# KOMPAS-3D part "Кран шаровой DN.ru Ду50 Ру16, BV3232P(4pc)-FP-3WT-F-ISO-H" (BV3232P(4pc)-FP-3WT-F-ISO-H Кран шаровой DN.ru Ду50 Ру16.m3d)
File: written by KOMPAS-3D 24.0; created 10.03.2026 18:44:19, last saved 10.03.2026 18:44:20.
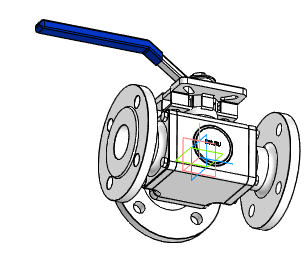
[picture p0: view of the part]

Document properties: Автор: R2D2; Полное имя файла: E:\Работа\Зайцев\BV3232P(4pc)-FP-3WT-F-ISO-H Кран шаровой DN.ru Ду15-100 Ру16\DN50\BV3232P(4pc)-FP-3WT-F-ISO-H Кран шаровой DN.ru Ду50 Ру16.m3d

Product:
- Part/product: Кран шаровой DN.ru Ду50 Ру16  | designation BV3232P(4pc)-FP-3WT-F-ISO-H
    Масса: 17.95
    Раздел спецификации: Прочие изделия
    Примечание: D160-36351

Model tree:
1. Операция без истории:1

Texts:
  BV3232P(4pc)-FP-3WT-F-ISO-H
